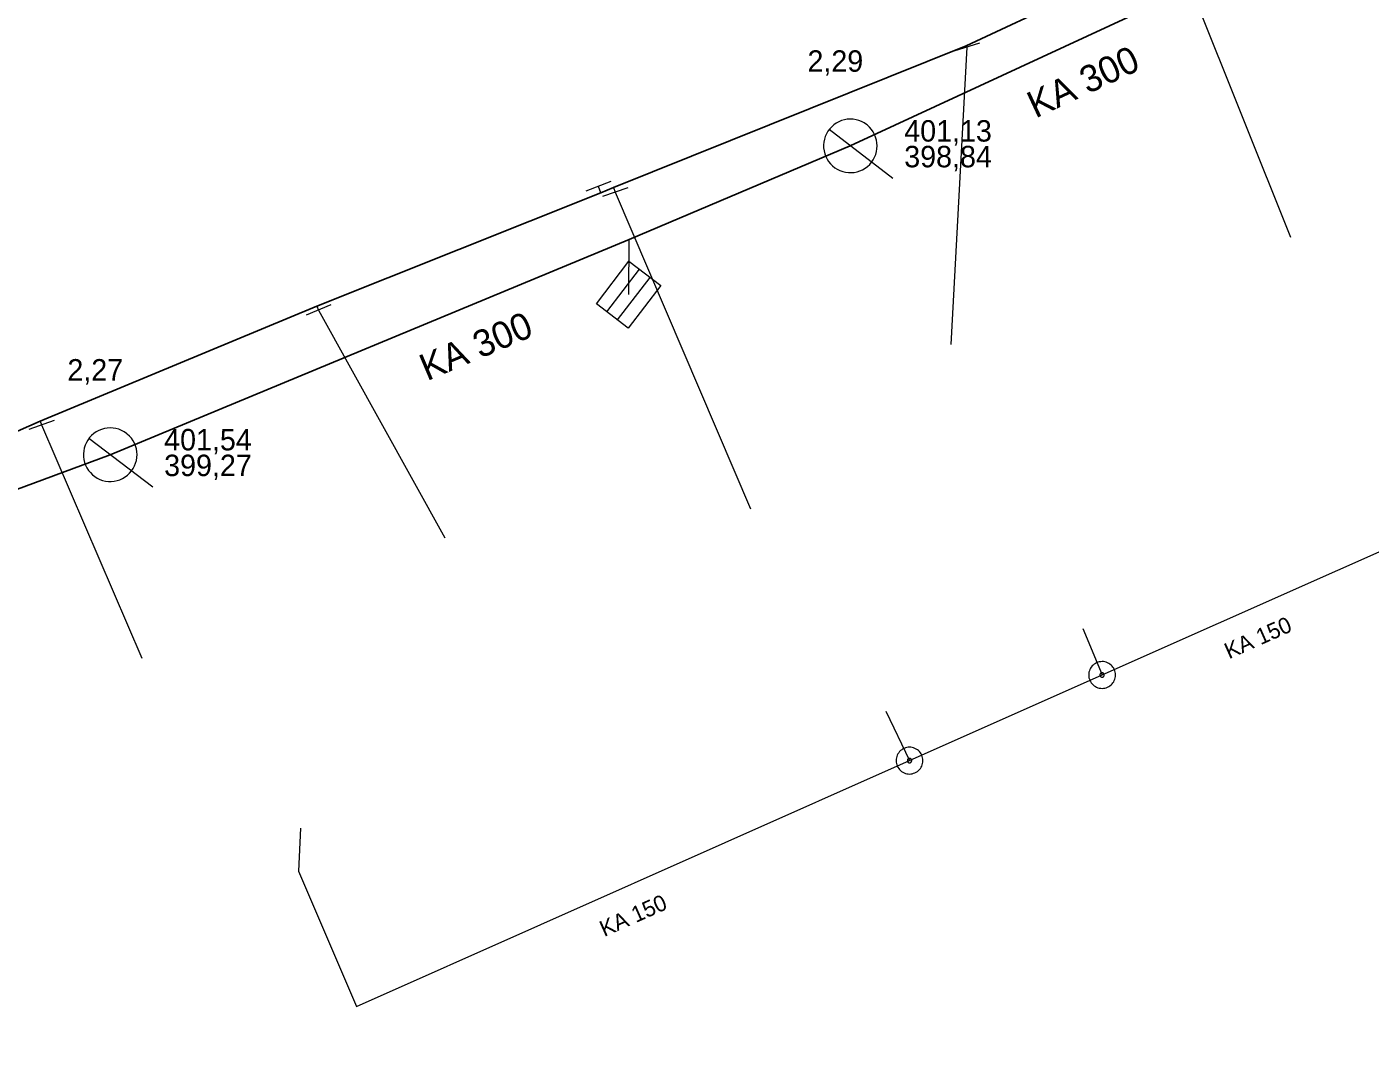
# Model space of a CAD drawing. Extents: x -809028 to -807737, y -990545 to -989489.
# Drawn here: x -808808.6 to -808758.4, y -990055 to -990016.5 of the extents above; entities that cross this region are included whole.
import ezdxf

# ---------------------------------------------------------------- set-up
doc = ezdxf.new("R2010")
doc.units = 0
doc.header["$LTSCALE"] = 0.32
for name, color, linetype, lineweight in [('1', 7, 'Continuous', 13), ('11', 7, 'Continuous', 13), ('13', 7, 'Continuous', 13), ('14', 7, 'Continuous', 25), ('17', 7, 'Continuous', 25), ('22', 7, 'Continuous', 13), ('31', 7, 'Continuous', 13), ('34', 7, 'Continuous', 13)]:
    doc.layers.add(name, color=color, linetype=linetype, lineweight=lineweight)

msp = doc.modelspace()

# ---------------------------------------------------------------- linework, layer by layer
at = {"layer": '11'}
for p, q in [((-808786.089, -990026.479), (-808786.079, -990024.42)), ((-808775.608, -990043.882), (-808768.417, -990040.685)), ((-808776.488, -990042.032), (-808775.608, -990043.882))]:
    msp.add_line(p, q, dxfattribs=at)
for points in [[(-808769.133, -990038.949), (-808768.417, -990040.685), (-808755.269, -990034.84)], [(-808798.355, -990046.41), (-808798.425, -990048.004), (-808796.256, -990053.061), (-808775.608, -990043.882)]]:
    msp.add_lwpolyline(points, dxfattribs=at)
at = {"layer": '13'}
for p, q in [((-808765.697, -990013.552), (-808761.384, -990024.342)), ((-808773.473, -990017.245), (-808774.066, -990028.349)), ((-808786.599, -990022.659), (-808781.544, -990034.478)), ((-808797.679, -990027.06), (-808792.962, -990035.561)), ((-808808.029, -990031.35), (-808804.274, -990040.052))]:
    msp.add_line(p, q, dxfattribs=at)
at = {"layer": '14'}
for p, q in [((-808777.819, -990020.93), (-808760.219, -990012.77)), ((-808831.909, -990042.27), (-808805.459, -990032.46))]:
    msp.add_line(p, q, dxfattribs=at)
at = {"layer": '14', "lineweight": 13}
for p, q in [((-808773.49, -990017.19), (-808773.473, -990017.245)), ((-808787.14, -990022.68), (-808787.229, -990022.44)), ((-808786.66, -990022.489), (-808786.599, -990022.659)), ((-808797.739, -990026.92), (-808797.679, -990027.06)), ((-808808.079, -990031.21), (-808808.029, -990031.35))]:
    msp.add_line(p, q, dxfattribs=at)
at = {"layer": '14'}
msp.add_lwpolyline([(-808805.459, -990032.46), (-808786.079, -990024.42), (-808777.819, -990020.93)], dxfattribs=at)
at = {"layer": '17'}
msp.add_lwpolyline([(-808759.931, -990010.868), (-808759.967, -990010.886), (-808765.697, -990013.552), (-808773.489, -990017.19), (-808786.66, -990022.489), (-808787.14, -990022.68), (-808797.739, -990026.92), (-808808.079, -990031.21), (-808813.62, -990033.649), (-808816.68, -990034.879), (-808826.25, -990038.68), (-808833.949, -990042.01), (-808853.449, -990050.44), (-808861.41, -990053.69), (-808874.829, -990059.1), (-808884.109, -990063.09), (-808885.989, -990063.91)], dxfattribs=at)
at = {"layer": '22'}
for p, q in [((-808776.23, -990022.145), (-808778.612, -990020.322)), ((-808786.907, -990027.125), (-808785.691, -990025.537)), ((-808786.51, -990027.429), (-808785.294, -990025.841)), ((-808803.87, -990033.675), (-808806.252, -990031.852))]:
    msp.add_line(p, q, dxfattribs=at)
for points in [[(-808777.21, -990020.136), (-808777.3, -990020.074), (-808777.397, -990020.023), (-808777.5, -990019.982), (-808777.604, -990019.953), (-808777.713, -990019.935), (-808777.822, -990019.93), (-808777.932, -990019.936), (-808778.039, -990019.955), (-808778.145, -990019.985), (-808778.246, -990020.026), (-808778.342, -990020.078), (-808778.432, -990020.141), (-808778.515, -990020.213), (-808778.589, -990020.293), (-808778.654, -990020.382), (-808778.709, -990020.476), (-808778.754, -990020.576), (-808778.787, -990020.681), (-808778.808, -990020.788), (-808778.818, -990020.896), (-808778.815, -990021.007), (-808778.801, -990021.115), (-808778.774, -990021.222), (-808778.737, -990021.324), (-808778.689, -990021.422), (-808778.629, -990021.514), (-808778.56, -990021.6), (-808778.483, -990021.677), (-808778.397, -990021.745), (-808778.304, -990021.803), (-808778.206, -990021.852), (-808778.103, -990021.888), (-808777.997, -990021.914), (-808777.888, -990021.928), (-808777.778, -990021.929), (-808777.67, -990021.919), (-808777.562, -990021.897), (-808777.458, -990021.863), (-808777.358, -990021.818), (-808777.264, -990021.762), (-808777.176, -990021.697), (-808777.096, -990021.622), (-808777.025, -990021.538), (-808776.963, -990021.448), (-808776.912, -990021.351), (-808776.871, -990021.25), (-808776.842, -990021.145), (-808776.824, -990021.036), (-808776.818, -990020.927), (-808776.824, -990020.818), (-808776.842, -990020.71), (-808776.873, -990020.604), (-808776.913, -990020.503), (-808776.966, -990020.407), (-808777.028, -990020.317), (-808777.1, -990020.234), (-808777.181, -990020.16)], [(-808787.304, -990026.822), (-808786.088, -990025.233), (-808784.897, -990026.145), (-808786.113, -990027.733)], [(-808804.85, -990031.666), (-808804.94, -990031.604), (-808805.037, -990031.553), (-808805.14, -990031.512), (-808805.244, -990031.483), (-808805.353, -990031.465), (-808805.462, -990031.46), (-808805.572, -990031.466), (-808805.679, -990031.485), (-808805.785, -990031.515), (-808805.886, -990031.556), (-808805.982, -990031.608), (-808806.072, -990031.671), (-808806.155, -990031.743), (-808806.229, -990031.823), (-808806.294, -990031.912), (-808806.349, -990032.006), (-808806.394, -990032.106), (-808806.427, -990032.211), (-808806.448, -990032.318), (-808806.458, -990032.426), (-808806.455, -990032.537), (-808806.441, -990032.645), (-808806.414, -990032.752), (-808806.377, -990032.854), (-808806.329, -990032.952), (-808806.269, -990033.044), (-808806.2, -990033.13), (-808806.123, -990033.207), (-808806.037, -990033.275), (-808805.944, -990033.333), (-808805.846, -990033.382), (-808805.743, -990033.418), (-808805.637, -990033.444), (-808805.528, -990033.458), (-808805.418, -990033.459), (-808805.31, -990033.449), (-808805.202, -990033.427), (-808805.098, -990033.393), (-808804.998, -990033.348), (-808804.904, -990033.292), (-808804.816, -990033.227), (-808804.736, -990033.152), (-808804.665, -990033.068), (-808804.603, -990032.978), (-808804.552, -990032.881), (-808804.511, -990032.78), (-808804.482, -990032.675), (-808804.464, -990032.566), (-808804.458, -990032.457), (-808804.464, -990032.348), (-808804.482, -990032.24), (-808804.513, -990032.134), (-808804.553, -990032.033), (-808804.606, -990031.937), (-808804.668, -990031.847), (-808804.74, -990031.764), (-808804.821, -990031.69)]]:
    msp.add_lwpolyline(points, close=True, dxfattribs=at)
at = {"layer": '31'}
for points in [[(-808767.96, -990040.481), (-808767.983, -990040.435), (-808768.012, -990040.391), (-808768.045, -990040.351), (-808768.081, -990040.313), (-808768.122, -990040.28), (-808768.167, -990040.252), (-808768.213, -990040.229), (-808768.262, -990040.21), (-808768.312, -990040.196), (-808768.364, -990040.187), (-808768.417, -990040.184), (-808768.469, -990040.188), (-808768.52, -990040.195), (-808768.571, -990040.209), (-808768.62, -990040.228), (-808768.666, -990040.251), (-808768.71, -990040.28), (-808768.751, -990040.313), (-808768.788, -990040.349), (-808768.821, -990040.39), (-808768.849, -990040.435), (-808768.873, -990040.482), (-808768.892, -990040.53), (-808768.906, -990040.58), (-808768.914, -990040.632), (-808768.917, -990040.685), (-808768.914, -990040.737), (-808768.906, -990040.788), (-808768.892, -990040.839), (-808768.873, -990040.888), (-808768.85, -990040.934), (-808768.821, -990040.978), (-808768.788, -990041.019), (-808768.752, -990041.056), (-808768.711, -990041.089), (-808768.667, -990041.118), (-808768.62, -990041.142), (-808768.571, -990041.161), (-808768.521, -990041.174), (-808768.469, -990041.182), (-808768.416, -990041.185), (-808768.365, -990041.182), (-808768.313, -990041.174), (-808768.262, -990041.16), (-808768.213, -990041.141), (-808768.167, -990041.118), (-808768.123, -990041.089), (-808768.082, -990041.057), (-808768.045, -990041.02), (-808768.012, -990040.979), (-808767.983, -990040.935), (-808767.96, -990040.889), (-808767.941, -990040.84), (-808767.928, -990040.789), (-808767.919, -990040.737), (-808767.916, -990040.684), (-808767.919, -990040.633), (-808767.927, -990040.581), (-808767.941, -990040.53)], [(-808768.342, -990040.651), (-808768.345, -990040.643), (-808768.35, -990040.636), (-808768.355, -990040.63), (-808768.361, -990040.624), (-808768.368, -990040.618), (-808768.376, -990040.614), (-808768.383, -990040.609), (-808768.391, -990040.606), (-808768.399, -990040.605), (-808768.408, -990040.603), (-808768.417, -990040.603), (-808768.425, -990040.603), (-808768.433, -990040.604), (-808768.442, -990040.606), (-808768.45, -990040.61), (-808768.458, -990040.613), (-808768.465, -990040.618), (-808768.471, -990040.623), (-808768.477, -990040.629), (-808768.483, -990040.636), (-808768.487, -990040.644), (-808768.492, -990040.651), (-808768.495, -990040.659), (-808768.497, -990040.668), (-808768.498, -990040.676), (-808768.498, -990040.685), (-808768.498, -990040.693), (-808768.497, -990040.701), (-808768.495, -990040.71), (-808768.491, -990040.718), (-808768.488, -990040.726), (-808768.483, -990040.733), (-808768.478, -990040.739), (-808768.472, -990040.745), (-808768.465, -990040.751), (-808768.458, -990040.756), (-808768.45, -990040.76), (-808768.442, -990040.763), (-808768.433, -990040.765), (-808768.425, -990040.766), (-808768.416, -990040.766), (-808768.408, -990040.766), (-808768.4, -990040.765), (-808768.391, -990040.763), (-808768.383, -990040.759), (-808768.375, -990040.756), (-808768.368, -990040.751), (-808768.362, -990040.746), (-808768.356, -990040.74), (-808768.35, -990040.733), (-808768.345, -990040.726), (-808768.341, -990040.718), (-808768.338, -990040.71), (-808768.337, -990040.702), (-808768.335, -990040.693), (-808768.335, -990040.684), (-808768.335, -990040.676), (-808768.336, -990040.668), (-808768.338, -990040.659)], [(-808775.151, -990043.678), (-808775.174, -990043.632), (-808775.203, -990043.588), (-808775.236, -990043.548), (-808775.272, -990043.51), (-808775.313, -990043.477), (-808775.358, -990043.449), (-808775.404, -990043.426), (-808775.453, -990043.407), (-808775.503, -990043.393), (-808775.555, -990043.384), (-808775.608, -990043.381), (-808775.66, -990043.385), (-808775.711, -990043.392), (-808775.762, -990043.406), (-808775.811, -990043.425), (-808775.857, -990043.448), (-808775.901, -990043.477), (-808775.942, -990043.51), (-808775.979, -990043.546), (-808776.012, -990043.587), (-808776.04, -990043.632), (-808776.064, -990043.679), (-808776.083, -990043.727), (-808776.097, -990043.777), (-808776.105, -990043.829), (-808776.108, -990043.882), (-808776.105, -990043.934), (-808776.097, -990043.985), (-808776.083, -990044.036), (-808776.064, -990044.085), (-808776.041, -990044.131), (-808776.012, -990044.175), (-808775.979, -990044.217), (-808775.943, -990044.253), (-808775.902, -990044.286), (-808775.858, -990044.315), (-808775.811, -990044.339), (-808775.762, -990044.358), (-808775.712, -990044.371), (-808775.66, -990044.379), (-808775.607, -990044.382), (-808775.556, -990044.379), (-808775.504, -990044.371), (-808775.453, -990044.357), (-808775.404, -990044.338), (-808775.358, -990044.315), (-808775.314, -990044.286), (-808775.273, -990044.254), (-808775.236, -990044.217), (-808775.203, -990044.176), (-808775.174, -990044.132), (-808775.151, -990044.086), (-808775.132, -990044.037), (-808775.119, -990043.986), (-808775.11, -990043.934), (-808775.107, -990043.881), (-808775.11, -990043.83), (-808775.118, -990043.778), (-808775.132, -990043.727)], [(-808775.533, -990043.848), (-808775.536, -990043.84), (-808775.541, -990043.833), (-808775.546, -990043.827), (-808775.552, -990043.821), (-808775.559, -990043.815), (-808775.567, -990043.811), (-808775.574, -990043.806), (-808775.582, -990043.803), (-808775.59, -990043.802), (-808775.599, -990043.8), (-808775.608, -990043.8), (-808775.616, -990043.8), (-808775.624, -990043.801), (-808775.633, -990043.803), (-808775.641, -990043.807), (-808775.649, -990043.81), (-808775.656, -990043.815), (-808775.662, -990043.82), (-808775.668, -990043.826), (-808775.674, -990043.833), (-808775.678, -990043.841), (-808775.683, -990043.848), (-808775.686, -990043.856), (-808775.688, -990043.865), (-808775.689, -990043.873), (-808775.689, -990043.882), (-808775.689, -990043.89), (-808775.688, -990043.898), (-808775.686, -990043.907), (-808775.682, -990043.915), (-808775.679, -990043.923), (-808775.674, -990043.93), (-808775.669, -990043.936), (-808775.663, -990043.942), (-808775.656, -990043.948), (-808775.649, -990043.953), (-808775.641, -990043.957), (-808775.633, -990043.96), (-808775.624, -990043.962), (-808775.616, -990043.963), (-808775.607, -990043.963), (-808775.599, -990043.963), (-808775.591, -990043.962), (-808775.582, -990043.96), (-808775.574, -990043.956), (-808775.566, -990043.953), (-808775.559, -990043.948), (-808775.553, -990043.943), (-808775.547, -990043.937), (-808775.541, -990043.93), (-808775.536, -990043.923), (-808775.532, -990043.915), (-808775.529, -990043.907), (-808775.528, -990043.899), (-808775.526, -990043.89), (-808775.526, -990043.881), (-808775.526, -990043.873), (-808775.527, -990043.865), (-808775.529, -990043.856)]]:
    msp.add_lwpolyline(points, close=True, dxfattribs=at)
at = {"layer": '34'}
for p, q in [((-808772.995, -990017.096), (-808773.95, -990017.392)), ((-808786.761, -990022.263), (-808787.697, -990022.615)), ((-808786.127, -990022.492), (-808787.07, -990022.824)), ((-808797.219, -990026.862), (-808798.138, -990027.256)), ((-808807.558, -990031.181), (-808808.5, -990031.517))]:
    msp.add_line(p, q, dxfattribs=at)

# ---------------------------------------------------------------- texts
at = {"layer": '1'}
for s, p in [('2,29', (-808779.419, -990018.161)), ('2,27', (-808807.059, -990029.691))]:
    msp.add_text(s, height=0.8, dxfattribs=at).set_placement(p)
for s, height, rotation, p in [('KA 300', 1, 25, (-808770.905, -990019.912)), ('KA 300', 1, 23, (-808793.628, -990029.719)), ('KA 150', 0.6, 24, (-808763.677, -990040.101)), ('KA 150', 0.6, 24, (-808787.011, -990050.473))]:
    msp.add_text(s, height=height, rotation=rotation, dxfattribs=at).set_placement(p)
at = {"layer": '14'}
for s, p in [('401,13', (-808775.805, -990020.769)), ('398,84', (-808775.805, -990021.729)), ('401,54', (-808803.445, -990032.299)), ('399,27', (-808803.445, -990033.259))]:
    msp.add_text(s, height=0.8, dxfattribs=at).set_placement(p)

doc.saveas('drawing.dxf')
